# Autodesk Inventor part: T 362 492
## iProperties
Created: 2005-06
Part Number: T 362 492
Material: 6PA45/1GF30
Document SubType Name: Modeling
Designer: I.Baliuc
Manufacturer: Standard
Standards Organization: Custom
Description: Schutzkappe
Density: 0.94 g/cm^3
Title: Schutzkappe
Company: Mayer & Müller AG Schaltgeräte
Zweck: Trenner Schaltrohr
Author: T.Messerschmitt
Revision Number: 362492
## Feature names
1. Extrusion2
2. Bezeichnung2 [Tagging]
